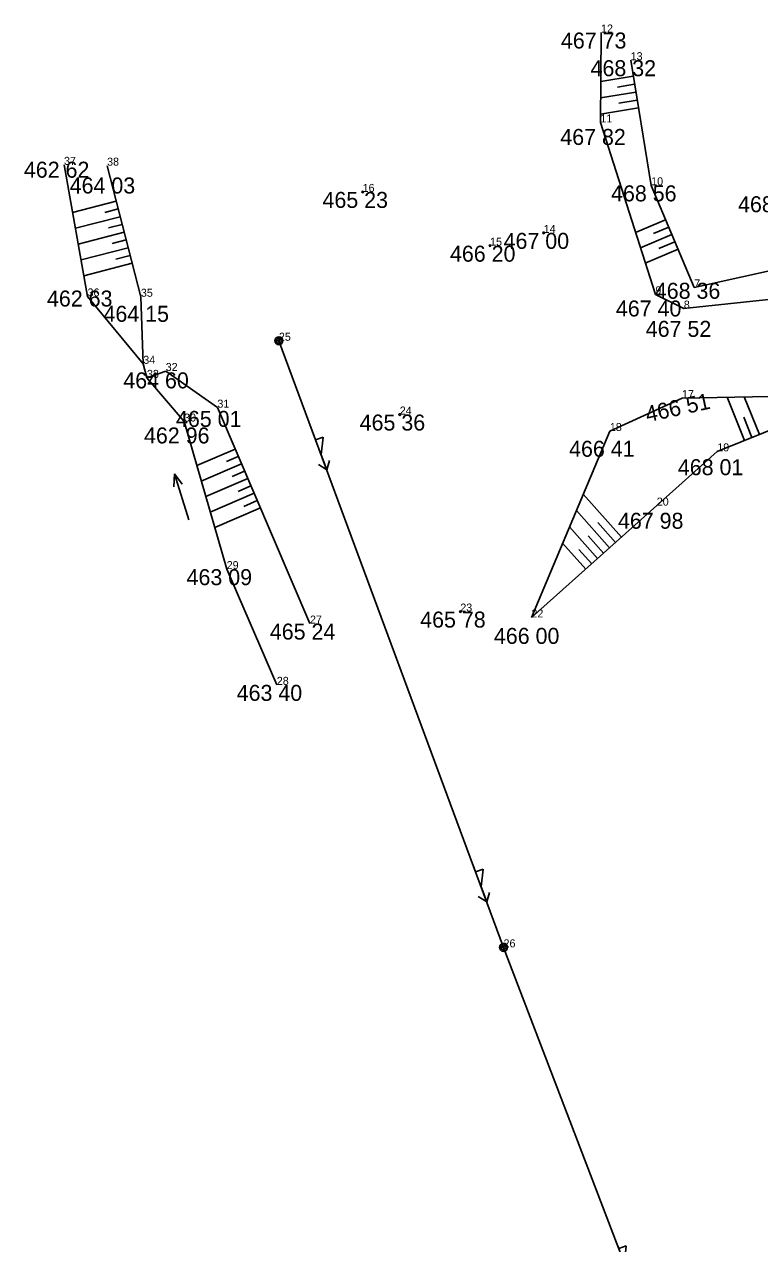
# Model space of a CAD drawing. Extents: x -559180 to -551373, y -1076947 to -1072071.
# Drawn here: x -553623.3 to -553577.4, y -1075615 to -1075538.8 of the extents above; entities that cross this region are included whole.
import ezdxf

# ---------------------------------------------------------------- set-up
doc = ezdxf.new("R2010")
doc.units = 0
for name, color, linetype in [('1_VODA_ZN', 7, 'Continuous'), ('20_EL_ZN', 7, 'Continuous'), ('23_HRANY', 7, 'Continuous'), ('26_SRAFY', 7, 'Continuous'), ('27_HRANA_PATA', 7, 'Continuous'), ('28_VODA', 7, 'Continuous'), ('3_BODY', 7, 'Continuous'), ('6_VYSKY', 7, 'Continuous'), ('NNnadzemní', 7, 'Continuous')]:
    doc.layers.add(name, color=color, linetype=linetype)

# ---------------------------------------------------------------- blocks, each defined once
blk = doc.blocks.new('T')
at = {"layer": '6_VYSKY'}
blk.add_circle((0, 0), 0.05, dxfattribs=at)
blk = doc.blocks.new('SLDP')
at = {"layer": '20_EL_ZN'}
for radius in [0.25, 0.158, 0.05]:
    blk.add_circle((0, 0), radius, dxfattribs=at)
blk = doc.blocks.new('VOTOK')
at = {"layer": '28_VODA'}
for p, q in [((-3, 0), (0, 0)), ((-0.75, 0.281), (0, 0)), ((0, 0), (-0.75, -0.281))]:
    blk.add_line(p, q, dxfattribs=at)
blk = doc.blocks.new('POINT_DISPLAY')
blk.add_line((0, 0), (0, 0))
blk = doc.blocks.new('ELNN')
at = {"layer": '20_EL_ZN'}
for p, q in [((0, 0), (0.5, 0)), ((0.5, 0), (0.5, 0.5)), ((0.5, 0.5), (1.5, 0)), ((1.5, 0), (2.5, 0))]:
    blk.add_line(p, q, dxfattribs=at)
blk.add_lwpolyline([(2, 0.375), (2.5, 0), (2, -0.375)], dxfattribs=at)

msp = doc.modelspace()

# ---------------------------------------------------------------- linework, layer by layer
at = {"layer": '23_HRANY'}
for p, q in [((-553615.92, -1075559.99), (-553616.07, -1075555.8)), ((-553615.69, -1075560.87), (-553615.92, -1075559.99))]:
    msp.add_line(p, q, dxfattribs=at)
at = {"layer": '26_SRAFY'}
for p, q in [((-553587.352, -1075542.361), (-553585.315, -1075542.028)), ((-553586.295, -1075542.695), (-553585.234, -1075542.521)), ((-553587.359, -1075543.376), (-553585.154, -1075543.015)), ((-553587.366, -1075544.39), (-553584.992, -1075544.001)), ((-553586.218, -1075543.695), (-553585.073, -1075543.508)), ((-553620.338, -1075550.534), (-553617.608, -1075549.831)), ((-553620.161, -1075551.521), (-553617.358, -1075550.799)), ((-553618.313, -1075550.529), (-553617.483, -1075550.315)), ((-553618.086, -1075551.503), (-553617.234, -1075551.283)), ((-553585.176, -1075551.779), (-553583.295, -1075550.986)), ((-553584.062, -1075551.852), (-553583.101, -1075551.447)), ((-553619.985, -1075552.508), (-553617.109, -1075551.767)), ((-553617.858, -1075552.477), (-553616.984, -1075552.252)), ((-553584.871, -1075552.736), (-553582.907, -1075551.908)), ((-553583.715, -1075552.791), (-553582.712, -1075552.368)), ((-553619.808, -1075553.496), (-553616.859, -1075552.736)), ((-553617.63, -1075553.451), (-553616.735, -1075553.22)), ((-553584.565, -1075553.692), (-553582.518, -1075552.829)), ((-553619.632, -1075554.483), (-553616.61, -1075553.704)), ((-553579.456, -1075562.081), (-553578.369, -1075564.773)), ((-553578.385, -1075562.062), (-553577.442, -1075564.399)), ((-553578.413, -1075563.329), (-553577.906, -1075564.586)), ((-553612.578, -1075566.345), (-553610.181, -1075565.318)), ((-553610.72, -1075566.093), (-553609.984, -1075565.778)), ((-553612.299, -1075567.313), (-553609.787, -1075566.237)), ((-553610.361, -1075567.027), (-553609.59, -1075566.697)), ((-553612.019, -1075568.282), (-553609.393, -1075567.156)), ((-553610.001, -1075567.961), (-553609.197, -1075567.616)), ((-553611.74, -1075569.25), (-553609, -1075568.076)), ((-553588.44, -1075568.137), (-553586.05, -1075570.814)), ((-553611.461, -1075570.218), (-553608.606, -1075568.995)), ((-553609.642, -1075568.895), (-553608.803, -1075568.535)), ((-553588.869, -1075569.158), (-553586.796, -1075571.48)), ((-553587.539, -1075569.897), (-553586.423, -1075571.147)), ((-553589.299, -1075570.178), (-553587.542, -1075572.146)), ((-553588.127, -1075570.741), (-553587.169, -1075571.813)), ((-553589.728, -1075571.199), (-553588.288, -1075572.812)), ((-553588.714, -1075571.584), (-553587.915, -1075572.479))]:
    msp.add_line(p, q, dxfattribs=at)
at = {"layer": '27_HRANA_PATA'}
for p, q in [((-553587.37, -1075544.91), (-553587.33, -1075539.29)), ((-553584.2, -1075548.84), (-553585.48, -1075541.02)), ((-553583.94, -1075555.65), (-553587.37, -1075544.91)), ((-553616.07, -1075555.8), (-553618.18, -1075547.61)), ((-553581.51, -1075555.22), (-553584.2, -1075548.84)), ((-553574.66, -1075553.69), (-553581.51, -1075555.22)), ((-553582.16, -1075556.54), (-553583.94, -1075555.65)), ((-553574.7, -1075555.73), (-553582.16, -1075556.54)), ((-553614.52, -1075560.44), (-553615.69, -1075560.87)), ((-553611.29, -1075562.73), (-553614.52, -1075560.44)), ((-553582.27, -1075562.13), (-553586.78, -1075564.19)), ((-553573.04, -1075561.97), (-553582.27, -1075562.13)), ((-553605.51, -1075576.22), (-553611.29, -1075562.73)), ((-553573.48, -1075562.8), (-553580.07, -1075565.46)), ((-553586.78, -1075564.19), (-553591.68, -1075575.84)), ((-553580.07, -1075565.46), (-553583.85, -1075568.85)), ((-553591.68, -1075575.84), (-553583.85, -1075568.85))]:
    msp.add_line(p, q, dxfattribs=at)
at = {"layer": '28_VODA'}
for p, q in [((-553619.4, -1075555.78), (-553620.87, -1075547.56)), ((-553615.92, -1075559.99), (-553619.4, -1075555.78)), ((-553613.37, -1075563.6), (-553615.69, -1075560.87)), ((-553610.71, -1075572.82), (-553613.37, -1075563.6)), ((-553607.58, -1075580.05), (-553610.71, -1075572.82))]:
    msp.add_line(p, q, dxfattribs=at)
at = {"layer": 'NNnadzemní'}
for p, q in [((-553593.42, -1075596.45), (-553607.45, -1075558.55)), ((-553582.39, -1075625.31), (-553593.42, -1075596.45))]:
    msp.add_line(p, q, dxfattribs=at)

# ---------------------------------------------------------------- block references
at = {"layer": '1_VODA_ZN'}
for p in [(-553587.33, -1075539.29), (-553585.48, -1075541.02), (-553587.37, -1075544.91), (-553620.87, -1075547.56), (-553618.18, -1075547.61), (-553602.22, -1075549.25), (-553584.2, -1075548.84), (-553590.91, -1075551.81), (-553594.26, -1075552.61), (-553581.51, -1075555.22), (-553619.4, -1075555.78), (-553616.07, -1075555.8), (-553583.94, -1075555.65), (-553582.16, -1075556.54), (-553607.45, -1075558.55), (-553615.92, -1075559.99), (-553614.52, -1075560.44), (-553615.69, -1075560.87), (-553582.27, -1075562.13), (-553611.29, -1075562.73), (-553613.37, -1075563.6), (-553599.9, -1075563.16), (-553586.78, -1075564.19), (-553580.07, -1075565.46), (-553583.85, -1075568.85), (-553610.71, -1075572.82), (-553596.12, -1075575.47), (-553591.68, -1075575.84), (-553605.51, -1075576.22), (-553607.58, -1075580.05), (-553593.42, -1075596.45)]:
    msp.add_blockref('POINT_DISPLAY', p, dxfattribs=at)
at = {"layer": '20_EL_ZN'}
for p in [(-553607.45, -1075558.55), (-553593.42, -1075596.45)]:
    msp.add_blockref('SLDP', p, dxfattribs=at)
for p, xscale, yscale, rotation in [((-553605.329, -1075564.279), 1.0000003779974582, 1.0000003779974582, -69.68627794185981), ((-553595.337, -1075591.271), 1.0000003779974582, 1.0000003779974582, -69.68627794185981), ((-553586.406, -1075614.803), 1.0000013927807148, 1.0000013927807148, -69.08368550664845)]:
    msp.add_blockref('ELNN', p, dxfattribs=dict(at, xscale=xscale, yscale=yscale, rotation=rotation))
at = {"layer": '28_VODA', "xscale": 1.0000010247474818, "yscale": 1.0000010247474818, "rotation": 107.58057668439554}
msp.add_blockref('VOTOK', (-553613.978, -1075566.87), dxfattribs=at)
at = {"layer": '6_VYSKY'}
for p in [(-553602.22, -1075549.25), (-553602.22, -1075549.25), (-553590.91, -1075551.81), (-553590.91, -1075551.81), (-553594.26, -1075552.61), (-553594.26, -1075552.61), (-553599.9, -1075563.16), (-553599.9, -1075563.16), (-553596.12, -1075575.47), (-553596.12, -1075575.47)]:
    msp.add_blockref('T', p, dxfattribs=at)

# ---------------------------------------------------------------- texts
at = {"layer": '3_BODY'}
for s, p in [('12', (-553587.33, -1075539.29)), ('13', (-553585.48, -1075541.02)), ('11', (-553587.37, -1075544.91)), ('37', (-553620.87, -1075547.56)), ('38', (-553618.18, -1075547.61)), ('10', (-553584.2, -1075548.84)), ('16', (-553602.22, -1075549.25)), ('14', (-553590.91, -1075551.81)), ('15', (-553594.26, -1075552.61)), ('7', (-553581.51, -1075555.22)), ('36', (-553619.4, -1075555.78)), ('35', (-553616.07, -1075555.8)), ('9', (-553583.94, -1075555.65)), ('8', (-553582.16, -1075556.54)), ('25', (-553607.45, -1075558.55)), ('34', (-553615.92, -1075559.99)), ('32', (-553614.52, -1075560.44)), ('33', (-553615.69, -1075560.87)), ('31', (-553611.29, -1075562.73)), ('17', (-553582.27, -1075562.13)), ('30', (-553613.37, -1075563.6)), ('24', (-553599.9, -1075563.16)), ('18', (-553586.78, -1075564.19)), ('19', (-553580.07, -1075565.46)), ('20', (-553583.85, -1075568.85)), ('29', (-553610.71, -1075572.82)), ('23', (-553596.12, -1075575.47)), ('27', (-553605.51, -1075576.22)), ('22', (-553591.68, -1075575.84)), ('28', (-553607.58, -1075580.05)), ('26', (-553593.42, -1075596.45))]:
    msp.add_text(s, height=0.5, dxfattribs=at).set_placement(p)
at = {"layer": '6_VYSKY'}
for s, p in [('467 73', (-553589.835, -1075540.29)), ('468 32', (-553587.985, -1075542.02)), ('467 82', (-553589.875, -1075546.316)), ('462 62', (-553623.375, -1075548.362)), ('464 03', (-553620.515, -1075549.349)), ('465 23', (-553604.725, -1075550.25)), ('468 56', (-553586.705, -1075549.84)), ('468 58', (-553578.775, -1075550.52)), ('467 00', (-553593.415, -1075552.81)), ('466 20', (-553596.765, -1075553.61)), ('462 63', (-553621.934, -1075556.411)), ('468 36', (-553583.972, -1075555.928)), ('467 40', (-553586.403, -1075557.033)), ('464 15', (-553618.404, -1075557.367)), ('467 52', (-553584.537, -1075558.306)), ('464 60', (-553617.167, -1075561.525)), ('465 01', (-553613.877, -1075563.933)), ('465 36', (-553602.405, -1075564.16)), ('462 96', (-553615.875, -1075564.966)), ('466 41', (-553589.326, -1075565.8)), ('468 01', (-553582.534, -1075566.948)), ('467 98', (-553586.273, -1075570.297)), ('463 09', (-553613.215, -1075573.82)), ('465 78', (-553598.625, -1075576.47)), ('465 24', (-553608.015, -1075577.22)), ('466 00', (-553594.022, -1075577.49)), ('463 40', (-553610.085, -1075581.05))]:
    msp.add_text(s, height=1, dxfattribs=at).set_placement(p)
msp.add_text('466 51', height=1, rotation=12.24545, dxfattribs=at).set_placement((-553584.438, -1075563.648))

doc.saveas('drawing.dxf')
